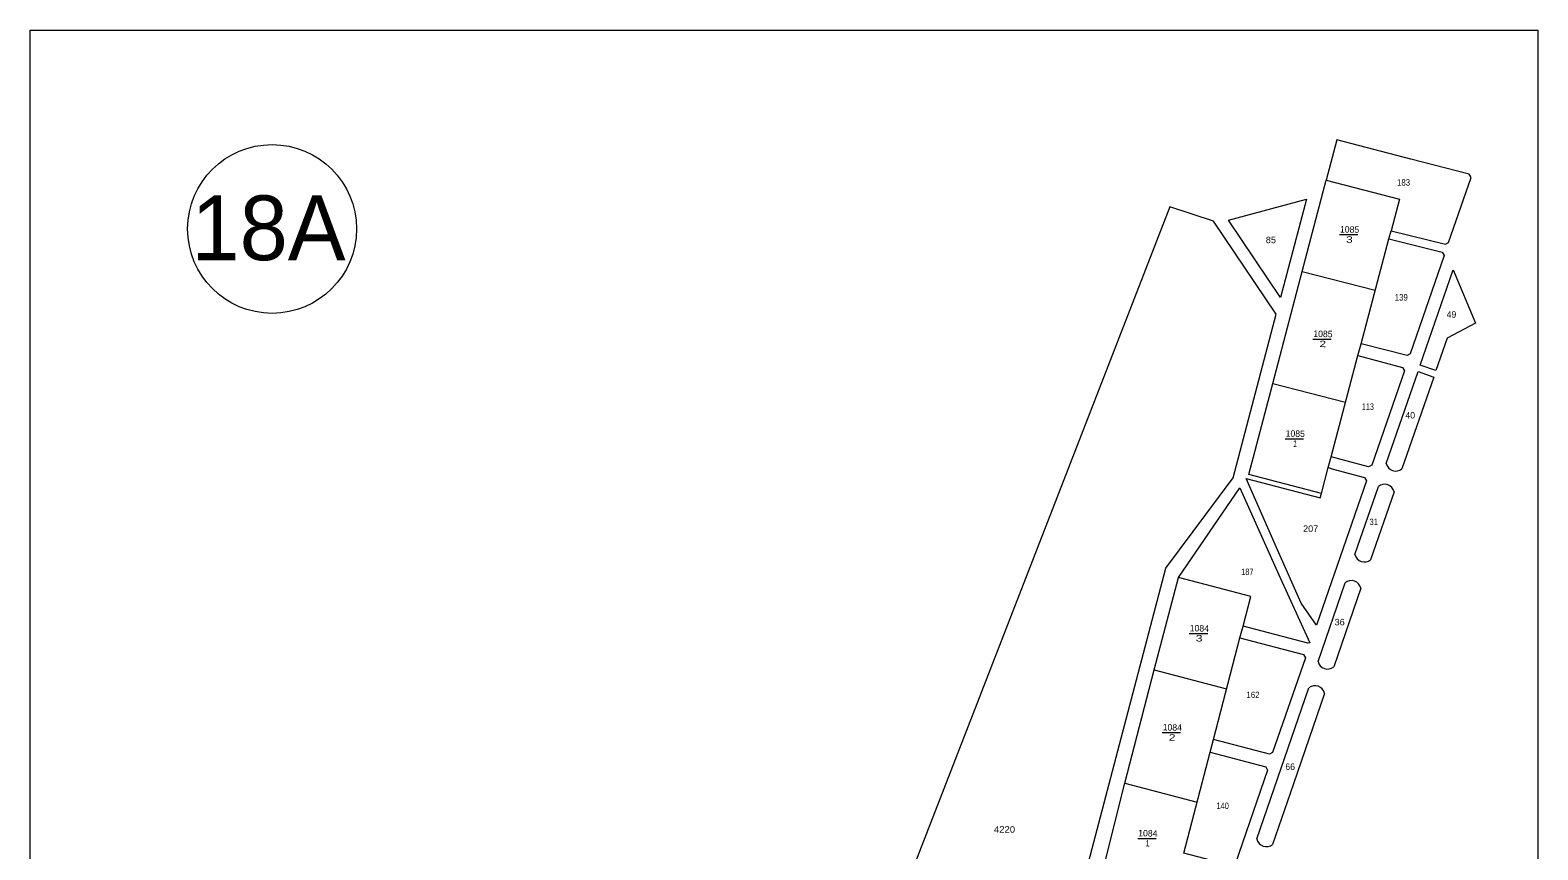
# Model space of a CAD drawing. Extents: x -843556 to -843323, y -1003151 to -1002684.
# Drawn here: x -843555.6 to -843322.7, y -1002810.3 to -1002683.6 of the extents above; entities that cross this region are included whole.
import ezdxf
from ezdxf.enums import TextEntityAlignment as Align

# ---------------------------------------------------------------- set-up
doc = ezdxf.new("R2010")
doc.units = 0
doc.header["$LTSCALE"] = 0.4
for name, color, linetype, lineweight in [('35', 7, 'Continuous', 13), ('38', 7, 'Continuous', 13), ('43', 7, 'Continuous', 13), ('44', 7, 'Continuous', 13)]:
    doc.layers.add(name, color=color, linetype=linetype, lineweight=lineweight)

msp = doc.modelspace()

# ---------------------------------------------------------------- linework, layer by layer
at = {"layer": '35'}
for p, q in [((-843353.325, -1002715.18), (-843350.471, -1002715.18)), ((-843357.442, -1002731.318), (-843354.588, -1002731.318)), ((-843361.72, -1002746.731), (-843358.866, -1002746.731)), ((-843376.527, -1002776.814), (-843373.673, -1002776.814)), ((-843380.708, -1002792.14), (-843377.854, -1002792.14)), ((-843384.486, -1002808.494), (-843381.632, -1002808.494))]:
    msp.add_line(p, q, dxfattribs=at)
at = {"layer": '38'}
for p, q in [((-843345.683, -1002715.839), (-843345.35, -1002714.585)), ((-843359.08, -1002720.87), (-843347.79, -1002723.77)), ((-843350.464, -1002733.864), (-843349.98, -1002732.039)), ((-843363.62, -1002738.17), (-843352.37, -1002741.06)), ((-843355.062, -1002751.195), (-843354.617, -1002749.52)), ((-843368.697, -1002777.519), (-843368.215, -1002775.674)), ((-843381.92, -1002782.46), (-843370.75, -1002785.38)), ((-843373.303, -1002795.162), (-843372.798, -1002793.228)), ((-843386.49, -1002799.97), (-843375.32, -1002802.89))]:
    msp.add_line(p, q, dxfattribs=at)
for points in [[(-843356.12, -1002755.18), (-843367.32, -1002752.27), (-843363.62, -1002738.17), (-843359.08, -1002720.87), (-843355.38, -1002706.78)], [(-843390.09, -1002814.34), (-843386.49, -1002799.97), (-843381.92, -1002782.46), (-843378.19, -1002768.18)]]:
    msp.add_lwpolyline(points, dxfattribs=at)
at = {"layer": '43'}
for p, q in [((-843346.085, -1002750.555), (-843341.19, -1002736.356)), ((-843350.929, -1002764.604), (-843347.312, -1002754.113)), ((-843344.892, -1002754.947), (-843348.509, -1002765.438)), ((-843356.632, -1002781.147), (-843352.442, -1002768.994)), ((-843350.022, -1002769.828), (-843354.212, -1002781.982)), ((-843366.091, -1002808.585), (-843358.045, -1002785.246))]:
    msp.add_line(p, q, dxfattribs=at)
for points in [[(-843344.049, -1002709.69), (-843344.059, -1002709.723), (-843345.35, -1002714.585), (-843336.954, -1002716.677), (-843336.479, -1002716.42), (-843333.006, -1002706.346), (-843333.286, -1002705.828), (-843342.294, -1002703.535), (-843353.739, -1002700.53), (-843355.38, -1002706.78)], [(-843362.424, -1002724.909), (-843370.477, -1002712.961), (-843358.436, -1002709.685)], [(-843379.548, -1002710.893), (-843422.29, -1002821.11), (-843447.677, -1002886.601), (-843435.31, -1002891.55), (-843426.04, -1002890.66), (-843415.4, -1002875.44), (-843403.14, -1002829.42), (-843392.58, -1002814.16), (-843380.16, -1002766.74), (-843369.72, -1002752.76), (-843363.099, -1002727.486), (-843372.788, -1002713.11)], [(-843345.683, -1002715.839), (-843337.454, -1002717.912), (-843337.172, -1002718.43), (-843342.411, -1002733.626), (-843342.892, -1002733.882), (-843349.98, -1002732.039)], [(-843335.764, -1002720.618), (-843332.33, -1002728.86), (-843336.699, -1002731.182), (-843338.43, -1002736.204), (-843340.85, -1002735.37)], [(-843350.464, -1002733.864), (-843343.579, -1002735.698), (-843343.304, -1002736.215), (-843348.336, -1002750.813), (-843348.817, -1002751.069), (-843354.617, -1002749.52)], [(-843355.062, -1002751.195), (-843354.3, -1002751.41), (-843349.44, -1002752.699), (-843349.165, -1002753.216), (-843356.862, -1002775.544), (-843359.218, -1002772.119), (-843362.9, -1002763.9), (-843367.736, -1002752.878), (-843356.292, -1002755.881), (-843356.12, -1002755.18)], [(-843378.19, -1002768.18), (-843368.726, -1002754.327), (-843362.69, -1002767.74), (-843357.91, -1002778.275), (-843358.208, -1002778.314), (-843368.215, -1002775.674), (-843367.02, -1002771.1)], [(-843368.697, -1002777.519), (-843358.873, -1002780.053), (-843358.595, -1002780.571), (-843363.649, -1002795.23), (-843364.128, -1002795.487), (-843372.798, -1002793.228)], [(-843373.303, -1002795.162), (-843364.697, -1002797.424), (-843364.42, -1002797.941), (-843369.418, -1002812.466), (-843369.898, -1002812.722), (-843377.382, -1002810.775)]]:
    msp.add_lwpolyline(points, close=True, dxfattribs=at)
for points in [[(-843341.19, -1002736.356), (-843338.77, -1002737.19), (-843343.665, -1002751.389)], [(-843355.625, -1002786.08), (-843360.445, -1002800.062), (-843363.672, -1002809.42)]]:
    msp.add_lwpolyline(points, dxfattribs=at)
for centre, start, end in [((-843344.62, -1002750.2319), 192.42745, 309.52883), ((-843346.3569, -1002755.2702), 12.42745, 129.52883), ((-843349.4635, -1002764.281), 192.42745, 309.52883), ((-843351.4872, -1002770.1512), 12.42745, 129.52883), ((-843355.1669, -1002780.8245), 192.42745, 309.52883), ((-843357.0901, -1002786.403), 12.42745, 129.52883), ((-843364.6263, -1002808.2626), 192.42745, 309.52883)]:
    msp.add_arc(centre, 1.5002, start, end, dxfattribs=at)
at = {"layer": '44'}
msp.add_lwpolyline([(-843322.682, -1002683.578), (-843322.682, -1003151.23), (-843555.557, -1003151.23), (-843555.557, -1002683.578)], close=True, dxfattribs=at)
msp.add_circle((-843518.1882, -1002714.3063), 13.0428, dxfattribs=at)

# ---------------------------------------------------------------- texts
at = {"layer": '35'}
for s, p in [('1085', (-843351.7675, -1002714.883)), ('1085', (-843355.8845, -1002731.021)), ('1085', (-843360.1625, -1002746.434)), ('1084', (-843374.97, -1002776.5174)), ('1084', (-843379.151, -1002791.8424)), ('1084', (-843382.9285, -1002808.1974))]:
    msp.add_text(s, height=1, rotation=358.734, dxfattribs=at).set_placement(p, align=Align.CENTER)
for s, width, p in [('3', 1.4, (-843351.8015, -1002716.4325)), ('2', 1.35, (-843355.918, -1002732.5713)), ('1', 0.7, (-843360.1965, -1002747.9838)), ('3', 1.4, (-843375.0035, -1002778.0665)), ('2', 1.35, (-843379.184, -1002793.3923)), ('1', 0.7, (-843382.9635, -1002809.7468))]:
    msp.add_text(s, height=1, rotation=358.734, dxfattribs=dict(at, width=width)).set_placement(p, align=Align.CENTER)
at = {"layer": '43'}
for s, width, p in [('183', 0.9, (-843344.426, -1002707.614)), ('85', 1.05, (-843364.694, -1002716.5)), ('139', 0.9, (-843344.783, -1002725.374)), ('113', 0.7, (-843349.873, -1002742.278)), ('31', 0.8, (-843348.684, -1002760.074)), ('207', 1.05, (-843358.948, -1002761.129)), ('187', 0.85, (-843368.497, -1002767.799)), ('36', 1.05, (-843354.073, -1002775.569)), ('162', 0.9, (-843367.682, -1002786.809)), ('140', 0.85, (-843372.307, -1002803.959)), ('4220', 1.1, (-843406.694, -1002807.607))]:
    msp.add_text(s, height=1, dxfattribs=dict(at, width=width)).set_placement(p)
for s, p in [('49', (-843336.767, -1002728.012)), ('40', (-843343.134, -1002743.603)), ('66', (-843361.676, -1002797.917))]:
    msp.add_text(s, height=1, dxfattribs=at).set_placement(p)
at = {"layer": '44'}
msp.add_text('18A', height=10, dxfattribs=at).set_placement((-843530.635, -1002719.133))

doc.saveas('drawing.dxf')
